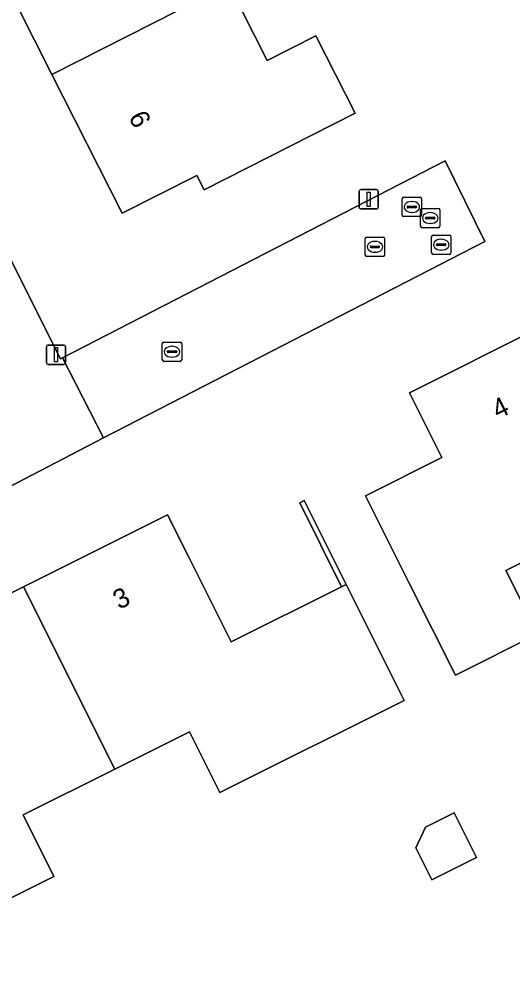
# Model space of a CAD drawing. Extents: x 162722 to 165104, y 384719 to 386284.
# Drawn here: x 163780.16 to 163805.66, y 384930.12 to 384979.9 of the extents above; entities that cross this region are included whole.
import ezdxf

# ---------------------------------------------------------------- set-up
doc = ezdxf.new("R2010")
doc.units = 0
for name, color, linetype in [('IMGEO_Brandkraan', 7, 'Continuous'), ('IMGEO_Erf', 7, 'Continuous'), ('IMGEO_Kolk', 7, 'Continuous'), ('IMGEO_Lichtmast', 7, 'Continuous'), ('IMGEO_Muur', 7, 'Continuous'), ('IMGEO_Pand', 7, 'Continuous'), ('IMGEO_Pand_nummerreeks', 7, 'Continuous'), ('IMGEO_Rijbaan_lokaal_open', 7, 'Continuous'), ('IMGEO_Rioolput', 7, 'Continuous'), ('IMGEO_Voetpad_open', 7, 'Continuous')]:
    doc.layers.add(name, color=color, linetype=linetype)

msp = doc.modelspace()

# ---------------------------------------------------------------- linework, layer by layer
at = {"layer": 'IMGEO_Brandkraan'}
for p, q in [((163801.467, 384967.827), (163801.467, 384968.679)), ((163801.542, 384968.753), (163802.394, 384968.753)), ((163802.468, 384968.679), (163802.468, 384967.827)), ((163801.726, 384968.247), (163801.726, 384968.259)), ((163802.164, 384968.21), (163801.766, 384968.21)), ((163801.769, 384968.296), (163802.167, 384968.296)), ((163801.955, 384968.533), (163801.98, 384968.533)), ((163802.21, 384968.259), (163802.21, 384968.247)), ((163802.394, 384967.753), (163801.542, 384967.753)), ((163801.978, 384967.973), (163801.953, 384967.973))]:
    msp.add_line(p, q, dxfattribs=at)
for points in [[(163801.467, 384967.827), (163801.467, 384968.679)], [(163801.542, 384968.753), (163802.394, 384968.753)], [(163802.468, 384968.679), (163802.468, 384967.827)], [(163802.394, 384967.753), (163801.542, 384967.753)]]:
    msp.add_lwpolyline(points, dxfattribs=at)
for centre, radius, start, end in [((163801.544, 384968.677), 0.0765, 91.552, 178.448), ((163801.544, 384968.677), 0.0765, 91.552, 178.448), ((163802.392, 384968.677), 0.0765, 1.552, 88.448), ((163802.392, 384968.677), 0.0765, 1.552, 88.448), ((163801.766, 384968.256), 0.0403, 85.8775, 175.7526), ((163801.763, 384968.246), 0.0366, 178.938, 274.7102), ((163802.167, 384968.253), 0.043, 264.8664, 352.4533), ((163802.171, 384968.258), 0.0386, 1.7309, 96.639), ((163801.544, 384967.829), 0.0765, 181.552, 268.448), ((163801.544, 384967.829), 0.0765, 181.552, 268.448), ((163802.392, 384967.829), 0.0765, 271.552, 358.448), ((163802.392, 384967.829), 0.0765, 271.552, 358.448)]:
    msp.add_arc(centre, radius, start, end, dxfattribs=at)
for centre, major_axis, ratio, start_param, end_param in [((163801.954, 384968.253), (-0.387, 0.002), 0.722429, 4.712389, 7.853982), ((163801.979, 384968.253), (-0.39, 0.002), 0.717154, 1.570796, 4.712389)]:
    msp.add_ellipse(centre, major_axis=major_axis, ratio=ratio, start_param=start_param, end_param=end_param, dxfattribs=at)
at = {"layer": 'IMGEO_Erf'}
for points in [[(163778.211, 384984.231), (163779.987, 384985.131), (163782.084, 384986.194), (163781.744, 384986.866), (163784.074, 384988.047), (163782.526, 384991.103), (163788.786, 384994.276), (163792.159, 384987.62), (163788.838, 384985.937), (163790.99, 384981.69), (163792.978, 384977.766), (163795.488, 384979.037), (163797.512, 384975.044), (163789.712, 384971.091), (163789.336, 384971.835), (163785.483, 384969.882), (163781.848, 384977.055)], [(163802.697, 384946.019), (163800.298, 384950.802), (163798.056, 384955.271), (163802.004, 384957.251), (163800.325, 384960.599), (163807.029, 384963.961), (163813.731, 384967.323), (163815.378, 384964.04), (163819.633, 384966.174), (163824.299, 384956.872), (163820.089, 384954.76), (163818.453, 384958.02), (163811.707, 384954.636), (163805.306, 384951.425), (163806.948, 384948.151)], [(163774.653, 384931.962), (163772.706, 384935.862), (163770.404, 384940.472), (163769.914, 384941.454), (163770.139, 384941.571), (163770.645, 384940.597), (163775.023, 384942.872), (163772.946, 384946.868), (163780.388, 384950.584), (163787.828, 384954.299), (163788.941, 384952.07), (163791.108, 384947.731), (163796.82, 384950.584), (163794.653, 384954.922), (163794.885, 384955.038), (163797.052, 384950.7), (163800.045, 384944.704), (163790.533, 384939.954), (163788.967, 384943.091), (163785.094, 384941.157), (163780.367, 384938.797), (163781.958, 384935.61)], [(163801.16, 384938.159), (163802.64, 384938.899), (163803.792, 384936.591), (163801.484, 384935.438), (163800.654, 384937.1)]]:
    msp.add_lwpolyline(points, close=True, dxfattribs=at)
msp.add_lwpolyline([(163773.478, 384979.9), (163782.291, 384962.358), (163782.404, 384962.416), (163802.16, 384972.581), (163804.226, 384968.418), (163784.518, 384958.283), (163775.869, 384953.781), (163770.816, 384948.556), (163767.966, 384945.654), (163759.567, 384936.98), (163755.864, 384933.157), (163744.141, 384921.063)], dxfattribs=at)
at = {"layer": 'IMGEO_Kolk'}
for p, q in [((163798.115, 384968.642), (163798.967, 384968.642)), ((163798.04, 384967.716), (163798.04, 384968.568)), ((163798.299, 384968.136), (163798.299, 384968.148)), ((163798.342, 384968.185), (163798.74, 384968.185)), ((163798.528, 384968.422), (163798.553, 384968.422)), ((163798.783, 384968.148), (163798.783, 384968.136)), ((163799.041, 384968.568), (163799.041, 384967.716)), ((163798.967, 384967.642), (163798.115, 384967.642)), ((163798.737, 384968.099), (163798.339, 384968.099)), ((163798.551, 384967.862), (163798.526, 384967.862)), ((163787.555, 384962.298), (163787.555, 384963.15)), ((163787.63, 384963.224), (163788.482, 384963.224)), ((163788.556, 384963.15), (163788.556, 384962.298)), ((163787.814, 384962.718), (163787.814, 384962.73)), ((163788.252, 384962.681), (163787.854, 384962.681)), ((163787.857, 384962.767), (163788.255, 384962.767)), ((163788.043, 384963.004), (163788.068, 384963.004)), ((163788.298, 384962.73), (163788.298, 384962.718)), ((163788.482, 384962.224), (163787.63, 384962.224)), ((163788.066, 384962.444), (163788.041, 384962.444))]:
    msp.add_line(p, q, dxfattribs=at)
for points in [[(163798.115, 384968.642), (163798.967, 384968.642)], [(163798.04, 384967.716), (163798.04, 384968.568)], [(163799.041, 384968.568), (163799.041, 384967.716)], [(163798.967, 384967.642), (163798.115, 384967.642)], [(163787.555, 384962.298), (163787.555, 384963.15)], [(163787.63, 384963.224), (163788.482, 384963.224)], [(163788.556, 384963.15), (163788.556, 384962.298)], [(163788.482, 384962.224), (163787.63, 384962.224)]]:
    msp.add_lwpolyline(points, dxfattribs=at)
for centre, radius, start, end in [((163798.117, 384968.566), 0.0765, 91.552, 178.448), ((163798.117, 384968.566), 0.0765, 91.552, 178.448), ((163798.965, 384968.566), 0.0765, 1.552, 88.448), ((163798.965, 384968.566), 0.0765, 1.552, 88.448), ((163798.339, 384968.145), 0.0403, 85.8775, 175.7526), ((163798.336, 384968.135), 0.0366, 178.938, 274.7102), ((163798.74, 384968.142), 0.043, 264.8664, 352.4533), ((163798.744, 384968.147), 0.0386, 1.7309, 96.639), ((163798.117, 384967.718), 0.0765, 181.552, 268.448), ((163798.117, 384967.718), 0.0765, 181.552, 268.448), ((163798.965, 384967.718), 0.0765, 271.552, 358.448), ((163798.965, 384967.718), 0.0765, 271.552, 358.448), ((163787.632, 384963.148), 0.0765, 91.552, 178.448), ((163787.632, 384963.148), 0.0765, 91.552, 178.448), ((163788.48, 384963.148), 0.0765, 1.552, 88.448), ((163788.48, 384963.148), 0.0765, 1.552, 88.448), ((163787.854, 384962.727), 0.0403, 85.8775, 175.7526), ((163787.851, 384962.717), 0.0366, 178.938, 274.7102), ((163788.255, 384962.724), 0.043, 264.8664, 352.4533), ((163788.259, 384962.729), 0.0386, 1.7309, 96.639), ((163787.632, 384962.3), 0.0765, 181.552, 268.448), ((163787.632, 384962.3), 0.0765, 181.552, 268.448), ((163788.48, 384962.3), 0.0765, 271.552, 358.448), ((163788.48, 384962.3), 0.0765, 271.552, 358.448)]:
    msp.add_arc(centre, radius, start, end, dxfattribs=at)
for centre, major_axis, ratio, start_param, end_param in [((163798.527, 384968.142), (-0.387, 0.002), 0.722429, 4.712389, 7.853982), ((163798.552, 384968.142), (-0.39, 0.002), 0.717154, 1.570796, 4.712389), ((163788.042, 384962.724), (-0.387, 0.002), 0.722429, 4.712389, 7.853982), ((163788.067, 384962.724), (-0.39, 0.002), 0.717154, 1.570796, 4.712389)]:
    msp.add_ellipse(centre, major_axis=major_axis, ratio=ratio, start_param=start_param, end_param=end_param, dxfattribs=at)
at = {"layer": 'IMGEO_Lichtmast'}
for p, q in [((163797.724, 384970.2), (163797.724, 384971)), ((163797.724, 384971), (163797.724, 384970.2)), ((163797.824, 384971.1), (163798.614, 384971.1)), ((163798.614, 384971.1), (163797.824, 384971.1)), ((163798.714, 384971), (163798.714, 384970.2)), ((163798.714, 384970.2), (163798.714, 384971)), ((163798.614, 384970.1), (163797.824, 384970.1)), ((163797.824, 384970.1), (163798.614, 384970.1)), ((163781.563, 384962.17), (163781.563, 384962.97)), ((163781.563, 384962.97), (163781.563, 384962.17)), ((163781.663, 384963.07), (163782.453, 384963.07)), ((163782.453, 384963.07), (163781.663, 384963.07)), ((163782.553, 384962.97), (163782.553, 384962.17)), ((163782.553, 384962.17), (163782.553, 384962.97)), ((163782.453, 384962.07), (163781.663, 384962.07)), ((163781.663, 384962.07), (163782.453, 384962.07))]:
    msp.add_line(p, q, dxfattribs=at)
for points in [[(163798.144, 384970.975), (163798.294, 384970.975), (163798.294, 384970.225), (163798.144, 384970.225), (163798.144, 384970.975)], [(163781.983, 384962.945), (163782.133, 384962.945), (163782.133, 384962.195), (163781.983, 384962.195), (163781.983, 384962.945)]]:
    msp.add_lwpolyline(points, dxfattribs=at)
for centre, start, end in [((163797.824, 384971), 90, 180), ((163797.824, 384971), 90, 180), ((163798.614, 384971), 0, 90), ((163798.614, 384971), 360, 90), ((163797.824, 384970.2), 180, 270), ((163797.824, 384970.2), 180, 270), ((163798.614, 384970.2), 270, 0), ((163798.614, 384970.2), 270, 0), ((163781.663, 384962.97), 90, 180), ((163781.663, 384962.97), 90, 180), ((163782.453, 384962.97), 0, 90), ((163782.453, 384962.97), 360, 90), ((163781.663, 384962.17), 180, 270), ((163781.663, 384962.17), 180, 270), ((163782.453, 384962.17), 270, 0), ((163782.453, 384962.17), 270, 0)]:
    msp.add_arc(centre, 0.1, start, end, dxfattribs=at)
at = {"layer": 'IMGEO_Muur'}
msp.add_lwpolyline([(163796.82, 384950.584), (163797.052, 384950.7), (163794.885, 384955.038), (163794.653, 384954.922)], close=True, dxfattribs=at)
at = {"layer": 'IMGEO_Pand'}
for points in [[(163790.99, 384981.69), (163788.838, 384985.937), (163792.159, 384987.62), (163788.786, 384994.276), (163782.526, 384991.103), (163784.074, 384988.047), (163781.744, 384986.866), (163782.084, 384986.194), (163779.987, 384985.131), (163778.211, 384984.231), (163781.848, 384977.055)], [(163781.848, 384977.055), (163785.483, 384969.882), (163789.336, 384971.835), (163789.712, 384971.091), (163797.512, 384975.044), (163795.488, 384979.037), (163792.978, 384977.766), (163790.99, 384981.69)], [(163807.029, 384963.961), (163800.325, 384960.599), (163802.004, 384957.251), (163798.056, 384955.271), (163800.298, 384950.802), (163802.697, 384946.019), (163806.948, 384948.151), (163805.306, 384951.425), (163811.707, 384954.636)], [(163785.094, 384941.157), (163788.967, 384943.091), (163790.533, 384939.954), (163800.045, 384944.704), (163797.052, 384950.7), (163796.82, 384950.584), (163791.108, 384947.731), (163788.941, 384952.07), (163787.828, 384954.299), (163780.388, 384950.584)], [(163780.388, 384950.584), (163772.946, 384946.868), (163775.023, 384942.872), (163770.645, 384940.597), (163770.404, 384940.472), (163772.706, 384935.862), (163774.653, 384931.962), (163781.958, 384935.61), (163780.367, 384938.797), (163785.094, 384941.157)], [(163800.654, 384937.1), (163801.484, 384935.438), (163803.792, 384936.591), (163802.64, 384938.899), (163801.16, 384938.159)]]:
    msp.add_lwpolyline(points, close=True, dxfattribs=at)
at = {"layer": 'IMGEO_Rijbaan_lokaal_open'}
msp.add_lwpolyline([(163784.518, 384958.283), (163804.226, 384968.418), (163802.16, 384972.581), (163782.404, 384962.416)], close=True, dxfattribs=at)
at = {"layer": 'IMGEO_Rioolput'}
for p, q in [((163799.946, 384969.776), (163799.946, 384970.628)), ((163800.021, 384970.702), (163800.873, 384970.702)), ((163800.947, 384970.628), (163800.947, 384969.776)), ((163800.205, 384970.196), (163800.205, 384970.208)), ((163800.643, 384970.159), (163800.245, 384970.159)), ((163800.248, 384970.245), (163800.646, 384970.245)), ((163800.434, 384970.482), (163800.459, 384970.482)), ((163800.689, 384970.208), (163800.689, 384970.196)), ((163800.975, 384970.13), (163801.827, 384970.13)), ((163800.873, 384969.702), (163800.021, 384969.702)), ((163800.457, 384969.922), (163800.432, 384969.922)), ((163800.9, 384969.204), (163800.9, 384970.056)), ((163801.159, 384969.624), (163801.159, 384969.636)), ((163801.202, 384969.673), (163801.6, 384969.673)), ((163801.388, 384969.91), (163801.413, 384969.91)), ((163801.643, 384969.636), (163801.643, 384969.624)), ((163801.901, 384970.056), (163801.901, 384969.204)), ((163801.827, 384969.13), (163800.975, 384969.13)), ((163801.597, 384969.587), (163801.199, 384969.587)), ((163801.411, 384969.35), (163801.386, 384969.35))]:
    msp.add_line(p, q, dxfattribs=at)
for points in [[(163799.946, 384969.776), (163799.946, 384970.628)], [(163800.021, 384970.702), (163800.873, 384970.702)], [(163800.947, 384970.628), (163800.947, 384969.776)], [(163800.975, 384970.13), (163801.827, 384970.13)], [(163800.873, 384969.702), (163800.021, 384969.702)], [(163800.9, 384969.204), (163800.9, 384970.056)], [(163801.901, 384970.056), (163801.901, 384969.204)], [(163801.827, 384969.13), (163800.975, 384969.13)]]:
    msp.add_lwpolyline(points, dxfattribs=at)
for centre, radius, start, end in [((163800.023, 384970.626), 0.0765, 91.552, 178.448), ((163800.023, 384970.626), 0.0765, 91.552, 178.448), ((163800.871, 384970.626), 0.0765, 1.552, 88.448), ((163800.871, 384970.626), 0.0765, 1.552, 88.448), ((163800.245, 384970.205), 0.0403, 85.8775, 175.7526), ((163800.242, 384970.195), 0.0366, 178.938, 274.7102), ((163800.646, 384970.202), 0.043, 264.8664, 352.4533), ((163800.65, 384970.207), 0.0386, 1.7309, 96.639), ((163800.977, 384970.054), 0.0765, 91.552, 178.448), ((163800.977, 384970.054), 0.0765, 91.552, 178.448), ((163801.825, 384970.054), 0.0765, 1.552, 88.448), ((163801.825, 384970.054), 0.0765, 1.552, 88.448), ((163800.023, 384969.778), 0.0765, 181.552, 268.448), ((163800.023, 384969.778), 0.0765, 181.552, 268.448), ((163800.871, 384969.778), 0.0765, 271.552, 358.448), ((163800.871, 384969.778), 0.0765, 271.552, 358.448), ((163801.199, 384969.633), 0.0403, 85.8775, 175.7526), ((163801.196, 384969.623), 0.0366, 178.938, 274.7102), ((163801.6, 384969.63), 0.043, 264.8664, 352.4533), ((163801.604, 384969.635), 0.0386, 1.7309, 96.639), ((163800.977, 384969.206), 0.0765, 181.552, 268.448), ((163800.977, 384969.206), 0.0765, 181.552, 268.448), ((163801.825, 384969.206), 0.0765, 271.552, 358.448), ((163801.825, 384969.206), 0.0765, 271.552, 358.448)]:
    msp.add_arc(centre, radius, start, end, dxfattribs=at)
for centre, major_axis, ratio, start_param, end_param in [((163800.433, 384970.202), (-0.387, 0.002), 0.722429, 4.712389, 7.853982), ((163800.458, 384970.202), (-0.39, 0.002), 0.717154, 1.570796, 4.712389), ((163801.387, 384969.63), (-0.387, 0.002), 0.722429, 4.712389, 7.853982), ((163801.412, 384969.63), (-0.39, 0.002), 0.717154, 1.570796, 4.712389)]:
    msp.add_ellipse(centre, major_axis=major_axis, ratio=ratio, start_param=start_param, end_param=end_param, dxfattribs=at)
at = {"layer": 'IMGEO_Voetpad_open'}
msp.add_lwpolyline([(163777.173, 384957.249), (163776.406, 384956.442), (163776.052, 384956.795), (163773.782, 384954.495), (163773.57, 384954.284), (163769.406, 384949.952), (163770.816, 384948.556), (163775.869, 384953.781), (163784.518, 384958.283), (163782.404, 384962.416), (163782.291, 384962.358), (163773.478, 384979.9)], dxfattribs=at)

# ---------------------------------------------------------------- texts
at = {"layer": 'IMGEO_Pand_nummerreeks'}
for s, rotation, p in [('6', 296.8757, (163785.789, 384974.853)), ('4', 26.6368, (163804.901, 384959.225)), ('3', 26.5337, (163785.326, 384949.384))]:
    msp.add_text(s, height=1, rotation=rotation, dxfattribs=at).set_placement(p)

doc.saveas('drawing.dxf')
